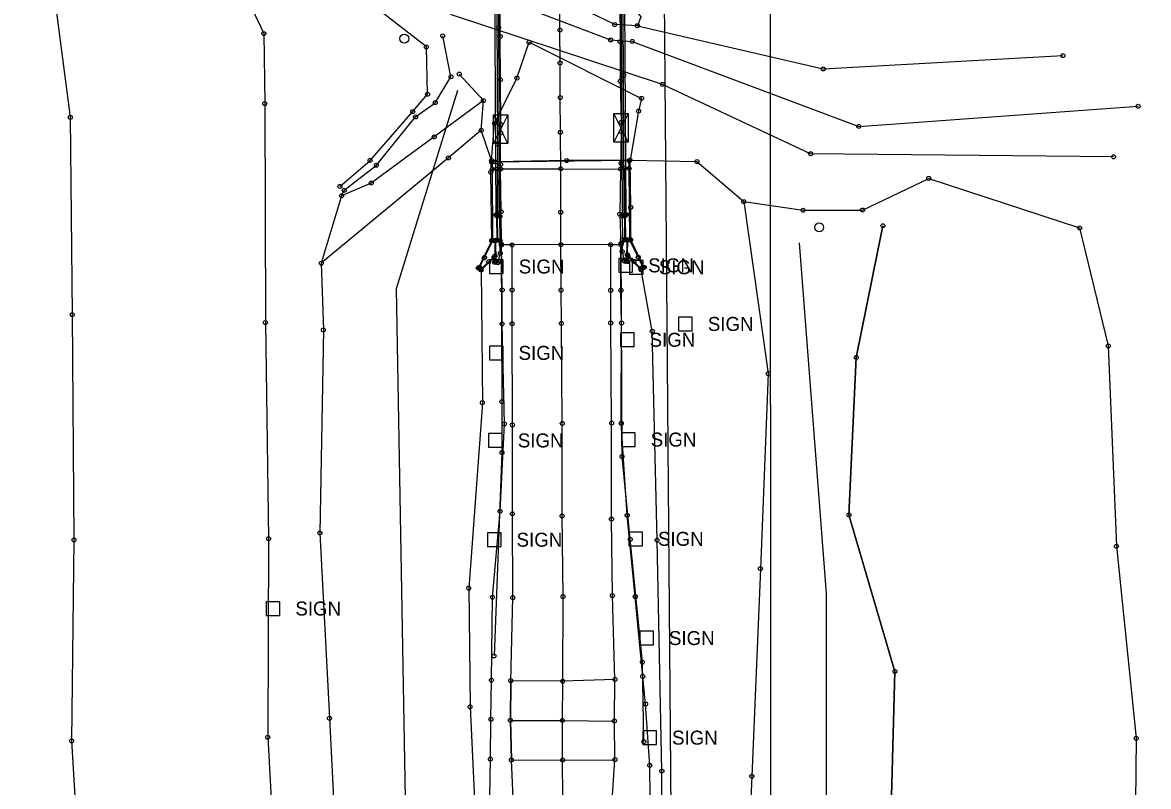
# Model space of a CAD drawing. Extents: x 23349949 to 23380641, y 6790552 to 6802878.
# Drawn here: x 23379697 to 23379978.9, y 6801650.8 to 6801841.9 of the extents above; entities that cross this region are included whole.
import ezdxf

# ---------------------------------------------------------------- set-up
doc = ezdxf.new("R2010")
doc.units = 0
for name, color, linetype in [('Bridge', 7, 'Continuous'), ('Default', 7, 'Continuous'), ('EXT_BL', 7, 'Continuous'), ('EXT_C', 7, 'Continuous'), ('EXT_CON', 7, 'Continuous'), ('EXT_D', 7, 'Continuous'), ('EXT_EP', 7, 'Continuous'), ('EXT_EW', 7, 'Continuous'), ('EXT_RIP', 7, 'Continuous'), ('EXT_SH', 7, 'Continuous'), ('Natural', 7, 'Continuous'), ('Roadways', 7, 'Continuous'), ('Section Lines', 7, 'Continuous'), ('SurControl', 7, 'Continuous'), ('SurPointsNonDTM', 7, 'Continuous'), ('SurRoadPoints', 7, 'Continuous'), ('SurSurveyPoints', 7, 'Continuous'), ('SurUtilityStructureCell', 7, 'Continuous'), ('UtilitiesBelowGround', 7, 'Continuous')]:
    doc.layers.add(name, color=color, linetype=linetype)

msp = doc.modelspace()

# ---------------------------------------------------------------- linework, layer by layer
at = {"layer": 'Bridge'}
for points in [[(23379814.83, 6801910.41), (23379814.87, 6801905.21), (23379815.27, 6801905.15), (23379815.35, 6801898.73), (23379815.45, 6801898.69), (23379815.66, 6801859.02), (23379815.96, 6801811.56), (23379816.02, 6801793.68), (23379815.84, 6801793.6), (23379815.92, 6801787.43), (23379815.4, 6801787.33), (23379815.49, 6801782.15), (23379816.23, 6801782.19), (23379816.62, 6801784.17), (23379816.59, 6801787.37), (23379816.53, 6801793.43), (23379816.24, 6801840.68), (23379815.98, 6801886.75), (23379815.92, 6801899.2), (23379815.94, 6801905.19), (23379815.96, 6801908.06), (23379815.42, 6801910.39)], [(23379848.31, 6801782.28), (23379848.38, 6801787.45), (23379847.85, 6801787.53), (23379847.84, 6801793.59), (23379847.64, 6801793.6), (23379847.49, 6801828.75), (23379847.2, 6801874.28), (23379847.05, 6801899.2), (23379847.23, 6801899.24), (23379847.26, 6801905.19), (23379847.75, 6801905.3), (23379847.7, 6801910.43), (23379846.98, 6801910.4), (23379846.55, 6801908.46), (23379846.57, 6801905.18), (23379846.59, 6801899.38), (23379846.88, 6801846.3), (23379847.19, 6801793.54), (23379847.21, 6801787.57), (23379847.15, 6801784.62), (23379847.64, 6801782.32)]]:
    msp.add_lwpolyline(points, close=True, dxfattribs=at)
at = {"layer": 'Default'}
for points in [[(23379831.81, 6801786.36), (23379831.76, 6801794.46), (23379831.79, 6801805.32), (23379831.69, 6801814.45), (23379831.67, 6801823.15), (23379831.62, 6801831.78), (23379831.56, 6801840.02), (23379831.43, 6801848.98), (23379831.5, 6801858.83), (23379831.27, 6801869.49), (23379831.42, 6801879.79), (23379831.28, 6801886.87), (23379831.24, 6801896.67), (23379831.13, 6801905.9)], [(23379815.61, 6801793.82), (23379815.02, 6801898.51)], [(23379848.16, 6801793.83), (23379847.48, 6801898.81)], [(23379846.57, 6801846.67), (23379846.64, 6801837.15), (23379846.66, 6801827.25), (23379846.91, 6801816.96), (23379846.91, 6801814.59), (23379846.74, 6801805.27), (23379846.54, 6801793.96), (23379846.83, 6801786.31), (23379844.29, 6801786.32), (23379831.81, 6801786.36), (23379819.6, 6801786.29), (23379816.92, 6801786.27), (23379816.88, 6801794.57), (23379816.71, 6801805.29), (23379816.71, 6801814.31), (23379816.77, 6801816.42), (23379816.68, 6801827.59), (23379816.63, 6801838.44), (23379816.55, 6801849.66)], [(23379816.87, 6801786.53), (23379817.05, 6801747.06), (23379817.05, 6801734.31), (23379815.07, 6801683.45)], [(23379852.58, 6801662), (23379852.22, 6801681.88), (23379849.16, 6801712.62), (23379847.12, 6801733.34), (23379846.9, 6801786.68)]]:
    msp.add_lwpolyline(points, dxfattribs=at)
at = {"layer": 'EXT_BL'}
for points in [[(23379703.1, 6801920.29), (23379702.18, 6801870.03), (23379709, 6801818.22), (23379709.48, 6801768.84), (23379709.92, 6801712.49), (23379709.34, 6801662.19), (23379712.14, 6801615.26), (23379714.4, 6801568.49), (23379697.04, 6801486.66)], [(23379776.48, 6801800.93), (23379784.04, 6801807.41), (23379794.71, 6801819.64), (23379798.43, 6801823.96), (23379798.13, 6801835.82), (23379770.13, 6801857.58), (23379767.46, 6801860.5), (23379737.65, 6801885.91), (23379703.1, 6801920.29)], [(23379746.93, 6801861.44), (23379757.45, 6801839.17), (23379757.68, 6801821.63), (23379757.83, 6801766.85), (23379758.62, 6801712.77), (23379758.42, 6801663.1), (23379760.97, 6801616.65), (23379762.46, 6801572), (23379761.99, 6801495.88)], [(23379776.9, 6801798.56), (23379777.57, 6801799.95), (23379785.63, 6801806.22), (23379795.45, 6801818.3), (23379800.36, 6801821.86), (23379804.3, 6801828.34), (23379802.23, 6801838.59)], [(23379816.03, 6801781.81), (23379815.25, 6801781.91), (23379815.04, 6801783.12), (23379811.82, 6801779.98), (23379811.17, 6801780.48), (23379814.49, 6801787.34), (23379814.27, 6801804.47), (23379814.47, 6801807.38), (23379811.86, 6801814.96), (23379812.43, 6801822.38), (23379806.38, 6801829.02)], [(23379812.43, 6801822.38), (23379800.09, 6801813.3), (23379784.33, 6801801.75), (23379776.9, 6801798.56), (23379771.83, 6801781.7)], [(23379811.86, 6801814.96), (23379803.64, 6801808.04), (23379771.83, 6801781.7), (23379772.35, 6801765.01), (23379771.47, 6801714.18), (23379771.48, 6801714.19), (23379773.88, 6801667.84), (23379776.35, 6801617.55), (23379776.91, 6801566.43), (23379779.21, 6801501.08)], [(23379849.15, 6801807.49), (23379833.25, 6801807.39), (23379815.5, 6801807.04), (23379814.47, 6801807.38)], [(23379851.87, 6801780.05), (23379852.67, 6801780.67), (23379849.3, 6801787.56), (23379849.29, 6801795.69), (23379849.15, 6801807.49), (23379865.87, 6801807.13), (23379877.6, 6801797.12), (23379892.44, 6801794.97), (23379907.31, 6801795), (23379923.88, 6801802.93), (23379961.65, 6801790.54)], [(23379816.71, 6801805.29), (23379831.79, 6801805.32), (23379846.74, 6801805.27)], [(23379877.6, 6801797.12), (23379883.73, 6801754.07), (23379881.76, 6801705.27), (23379879.61, 6801653.36), (23379877.45, 6801603.84), (23379879.08, 6801551.92), (23379880.22, 6801500.65)], [(23379921.53, 6801478.35), (23379918.04, 6801518.9), (23379919.73, 6801560.1), (23379911.12, 6801600.29), (23379914.15, 6801632.72), (23379915.42, 6801679.56), (23379903.91, 6801718.73), (23379905.76, 6801758.12), (23379912.41, 6801791.06)], [(23379961.65, 6801790.54), (23379968.85, 6801761.01), (23379970.88, 6801710.89), (23379975.83, 6801662.84), (23379975.22, 6801606.12), (23379978.9, 6801558.4), (23379972.44, 6801483.27)], [(23379857.85, 6801498.08), (23379857.65, 6801549.54), (23379857.24, 6801605.84), (23379857.08, 6801654.63), (23379855.9, 6801712.41), (23379854.7, 6801764.68), (23379851.87, 6801780.05), (23379848.61, 6801783.39), (23379848.48, 6801782.12), (23379847.85, 6801782.14)], [(23379811.82, 6801779.98), (23379812.16, 6801746.8), (23379808.74, 6801700.4), (23379809.09, 6801670.71), (23379810.92, 6801631.35), (23379810.84, 6801581.92), (23379810.59, 6801538.25), (23379810.38, 6801494.02)]]:
    msp.add_lwpolyline(points, dxfattribs=at)
at = {"layer": 'EXT_C'}
msp.add_lwpolyline([(23379833.11, 6801506.12), (23379832.79, 6801538.15), (23379832.81, 6801560.52), (23379832.69, 6801582.8), (23379832.58, 6801604.47), (23379832.48, 6801625.87), (23379832.33, 6801647.85), (23379832.25, 6801657.38), (23379832.21, 6801667.3), (23379832.28, 6801677.12), (23379832.35, 6801698.29), (23379832.11, 6801718.47), (23379832.17, 6801741.62), (23379831.95, 6801766.64), (23379831.84, 6801774.96), (23379831.81, 6801786.36)], dxfattribs=at)
at = {"layer": 'EXT_CON'}
msp.add_lwpolyline([(23379848.9, 6801805.42), (23379848.92, 6801807.36), (23379814.49, 6801806.98), (23379814.66, 6801805.22)], dxfattribs=at)
for points in [[(23379811.79, 6801780.24), (23379811.4, 6801780.66), (23379812.61, 6801783.03), (23379812.69, 6801783.14), (23379814.75, 6801787.38), (23379814.66, 6801805.22), (23379815.85, 6801805.26), (23379815.89, 6801793.73), (23379815.71, 6801793.6), (23379815.79, 6801787.46), (23379815.29, 6801787.44), (23379815.28, 6801783.5), (23379813.76, 6801782.06)], [(23379851.84, 6801780.4), (23379852.35, 6801780.71), (23379851.22, 6801783.13), (23379851.18, 6801783.2), (23379849.07, 6801787.49), (23379848.9, 6801805.42), (23379847.73, 6801805.48), (23379847.77, 6801793.73), (23379847.93, 6801793.68), (23379847.95, 6801787.6), (23379848.49, 6801787.57), (23379848.43, 6801783.84), (23379850.1, 6801782.17)], [(23379819.42, 6801657.42), (23379832.25, 6801657.38), (23379845.34, 6801657.48), (23379845.21, 6801667.16), (23379845.34, 6801677.56), (23379832.28, 6801677.12), (23379819.26, 6801677.25), (23379819.18, 6801667.32)]]:
    msp.add_lwpolyline(points, close=True, dxfattribs=at)
at = {"layer": 'EXT_D'}
for p, q in [((23379898.3, 6801699.04), (23379891.52, 6801786.79)), ((23379898.3, 6801496.16), (23379898.3, 6801699.04))]:
    msp.add_line(p, q, dxfattribs=at)
for points in [[(23379716.88, 6801938.56), (23379783.77, 6801873.05), (23379807.83, 6801852.6), (23379824.65, 6801845.04), (23379844.27, 6801837.55), (23379849.69, 6801837.18), (23379906.39, 6801815.92), (23379976.3, 6801820.96)], [(23379793.51, 6801494.6), (23379794.74, 6801546.37), (23379793.6, 6801609.98), (23379790.63, 6801775.37), (23379806.04, 6801824.96)]]:
    msp.add_lwpolyline(points, dxfattribs=at)
at = {"layer": 'EXT_EP'}
for points in [[(23379820.67, 6801506.94), (23379820.4, 6801537.92), (23379820.29, 6801561.41), (23379820.22, 6801582.8), (23379819.98, 6801604.58), (23379819.95, 6801625.47), (23379819.9, 6801647.82), (23379819.42, 6801657.42), (23379819.18, 6801667.32), (23379819.26, 6801677.25), (23379819.77, 6801698.03), (23379819.68, 6801719.01), (23379819.66, 6801741.23), (23379819.61, 6801766.55), (23379819.6, 6801775), (23379819.6, 6801786.29)], [(23379845.18, 6801510.36), (23379845.15, 6801538.43), (23379844.89, 6801559.01), (23379844.87, 6801582.96), (23379844.91, 6801604.33), (23379844.79, 6801625.84), (23379844.64, 6801647.35), (23379845.34, 6801657.48), (23379845.21, 6801667.16), (23379845.34, 6801677.56), (23379844.69, 6801698.54), (23379844.48, 6801717.68), (23379844.52, 6801741.69), (23379844.29, 6801766.73), (23379844.29, 6801774.92), (23379844.29, 6801786.32)]]:
    msp.add_lwpolyline(points, dxfattribs=at)
at = {"layer": 'EXT_EW'}
for points in [[(23379970.15, 6801808.32), (23379894.32, 6801809.09), (23379857.26, 6801826.44), (23379804.4, 6801843.87), (23379780.59, 6801866.66), (23379707.76, 6801932.18)], [(23379850.96, 6801841.13), (23379897.47, 6801830.3), (23379957.47, 6801833.63)]]:
    msp.add_lwpolyline(points, dxfattribs=at)
at = {"layer": 'EXT_RIP'}
for points in [[(23379846.86, 6801877.14), (23379844, 6801867.98), (23379840.23, 6801863.95), (23379841.16, 6801856.51), (23379851.79, 6801843.36), (23379850.97, 6801841.13), (23379845.29, 6801841.41), (23379834.85, 6801846.44), (23379830.07, 6801850.42), (23379820.55, 6801850.16), (23379807.1, 6801859.67), (23379799.92, 6801867.87), (23379801.87, 6801871.86), (23379808.43, 6801866.75), (23379811.52, 6801876.02), (23379808.2, 6801882.34), (23379825.53, 6801884.97)], [(23379833.25, 6801807.39), (23379815.5, 6801807.04), (23379814.47, 6801807.38), (23379815.21, 6801816.68), (23379820.81, 6801828.04), (23379823.87, 6801836.97), (23379852.01, 6801822.95), (23379851.27, 6801819.76), (23379849.15, 6801807.49)]]:
    msp.add_lwpolyline(points, dxfattribs=at)
at = {"layer": 'EXT_SH'}
for points in [[(23379812.05, 6801507.78), (23379812.63, 6801537.87), (23379812.74, 6801561.9), (23379812.93, 6801581.9), (23379813.55, 6801605.08), (23379813.63, 6801625.46), (23379814.05, 6801648.21), (23379814.16, 6801657.62), (23379814.31, 6801667.59), (23379814.43, 6801677.38), (23379814.68, 6801698.14), (23379816.59, 6801719.65), (23379817.67, 6801741.51), (23379817.1, 6801766.53), (23379817.1, 6801766.53), (23379817.11, 6801775.01), (23379816.92, 6801786.27)], [(23379856.05, 6801510.07), (23379855.87, 6801538.61), (23379856.07, 6801557.88), (23379855.92, 6801583.82), (23379855.68, 6801604.16), (23379855.06, 6801625.22), (23379854.13, 6801647.68), (23379854.07, 6801656.07), (23379853.02, 6801671.41), (23379852.3, 6801678.32), (23379850.44, 6801698.27), (23379848.4, 6801718.64), (23379846.94, 6801741.66), (23379847, 6801766.75), (23379846.85, 6801774.91), (23379846.83, 6801786.31)]]:
    msp.add_lwpolyline(points, dxfattribs=at)
at = {"layer": 'Natural'}
msp.add_lwpolyline([(23379912.41, 6801791.06), (23379905.76, 6801758.12), (23379903.91, 6801718.73), (23379915.42, 6801679.56), (23379914.15, 6801632.72), (23379911.12, 6801600.29), (23379919.73, 6801560.1), (23379918.04, 6801518.9), (23379921.53, 6801478.35)], dxfattribs=at)
at = {"layer": 'Roadways'}
msp.add_lwpolyline([(23379819.18, 6801667.32), (23379832.21, 6801667.3), (23379845.21, 6801667.16)], dxfattribs=at)
at = {"layer": 'Section Lines'}
msp.add_line((23379862.42, 6801260.03), (23379853.19, 6802427.68), dxfattribs=at)
at = {"layer": 'SurControl'}
for centre in [(23379792.6, 6801837.9), (23379896.47, 6801790.67)]:
    msp.add_circle(centre, 1.12, dxfattribs=at)
at = {"layer": 'SurPointsNonDTM'}
for centre in [(23379816.24, 6801840.68), (23379831.56, 6801840.02), (23379816.63, 6801838.44), (23379846.64, 6801837.15), (23379831.62, 6801831.78), (23379847.49, 6801828.75), (23379816.68, 6801827.59), (23379846.66, 6801827.25), (23379831.67, 6801823.15), (23379846.91, 6801816.96), (23379816.71, 6801814.31), (23379816.77, 6801816.42), (23379831.69, 6801814.45), (23379846.91, 6801814.59), (23379815.96, 6801811.56), (23379816.7, 6801806.42), (23379846.88, 6801806.68), (23379816.71, 6801805.29), (23379831.79, 6801805.32), (23379846.74, 6801805.27), (23379816.88, 6801794.57), (23379831.76, 6801794.46), (23379815.61, 6801793.82), (23379815.84, 6801793.6), (23379816.02, 6801793.68), (23379816.53, 6801793.43), (23379846.54, 6801793.96), (23379847.19, 6801793.54), (23379847.64, 6801793.6), (23379847.84, 6801793.59), (23379848.16, 6801793.83), (23379912.41, 6801791.06), (23379815.4, 6801787.33), (23379815.92, 6801787.43), (23379816.59, 6801787.37), (23379816.87, 6801786.53), (23379816.92, 6801786.27), (23379816.92, 6801786.27), (23379819.6, 6801786.29), (23379819.6, 6801786.29), (23379831.81, 6801786.36), (23379831.81, 6801786.36), (23379844.29, 6801786.32), (23379846.83, 6801786.31), (23379846.83, 6801786.31), (23379846.9, 6801786.68), (23379847.21, 6801787.57), (23379847.85, 6801787.53), (23379848.38, 6801787.45), (23379816.62, 6801784.17), (23379847.15, 6801784.62), (23379815.49, 6801782.15), (23379816.23, 6801782.19), (23379847.64, 6801782.32), (23379848.31, 6801782.28), (23379848.31, 6801782.28), (23379905.76, 6801758.12), (23379817.05, 6801747.06), (23379817.05, 6801734.31), (23379847.12, 6801733.34), (23379903.91, 6801718.73), (23379849.16, 6801712.62), (23379815.07, 6801683.45), (23379852.22, 6801681.88), (23379915.42, 6801679.56), (23379819.18, 6801667.32), (23379832.21, 6801667.3), (23379845.21, 6801667.16), (23379852.58, 6801662)]:
    msp.add_circle(centre, 0.5, dxfattribs=at)
at = {"layer": 'SurRoadPoints'}
for points in [[(23379815.67, 6801779.16), (23379815.67, 6801779.16), (23379817.38, 6801779.16), (23379817.38, 6801782.58), (23379813.95, 6801782.58), (23379813.95, 6801779.16), (23379815.67, 6801779.16)], [(23379848.06, 6801779.44), (23379848.06, 6801779.44), (23379849.77, 6801779.44), (23379849.77, 6801782.87), (23379846.34, 6801782.87), (23379846.34, 6801779.44), (23379848.05, 6801779.44)], [(23379850.72, 6801778.99), (23379850.72, 6801778.99), (23379852.44, 6801778.99), (23379852.44, 6801782.41), (23379849.01, 6801782.41), (23379849.01, 6801778.99), (23379850.72, 6801778.99)], [(23379862.99, 6801764.8), (23379862.99, 6801764.8), (23379864.71, 6801764.8), (23379864.71, 6801768.23), (23379861.28, 6801768.23), (23379861.28, 6801764.8), (23379862.99, 6801764.8)], [(23379848.41, 6801760.84), (23379848.41, 6801760.84), (23379850.12, 6801760.84), (23379850.12, 6801764.26), (23379846.7, 6801764.26), (23379846.7, 6801760.84), (23379848.41, 6801760.84)], [(23379815.61, 6801757.55), (23379815.61, 6801757.55), (23379817.33, 6801757.55), (23379817.33, 6801760.98), (23379813.9, 6801760.98), (23379813.9, 6801757.55), (23379815.61, 6801757.55)], [(23379815.42, 6801735.65), (23379815.42, 6801735.65), (23379817.13, 6801735.65), (23379817.13, 6801739.07), (23379813.71, 6801739.07), (23379813.71, 6801735.65), (23379815.42, 6801735.65)], [(23379848.68, 6801735.87), (23379848.68, 6801735.87), (23379850.4, 6801735.87), (23379850.4, 6801739.29), (23379846.97, 6801739.29), (23379846.97, 6801735.87), (23379848.68, 6801735.87)], [(23379815.11, 6801710.81), (23379815.11, 6801710.81), (23379816.82, 6801710.81), (23379816.82, 6801714.23), (23379813.4, 6801714.23), (23379813.4, 6801710.81), (23379815.11, 6801710.81)], [(23379850.51, 6801711.02), (23379850.51, 6801711.02), (23379852.22, 6801711.02), (23379852.22, 6801714.45), (23379848.79, 6801714.45), (23379848.79, 6801711.02), (23379850.51, 6801711.02)], [(23379759.73, 6801693.59), (23379759.73, 6801693.59), (23379761.45, 6801693.59), (23379761.45, 6801697.02), (23379758.02, 6801697.02), (23379758.02, 6801693.59), (23379759.73, 6801693.59)], [(23379853.25, 6801686.2), (23379853.25, 6801686.2), (23379854.96, 6801686.2), (23379854.96, 6801689.62), (23379851.54, 6801689.62), (23379851.54, 6801686.2), (23379853.25, 6801686.2)], [(23379854.02, 6801661.29), (23379854.02, 6801661.29), (23379855.74, 6801661.29), (23379855.74, 6801664.71), (23379852.31, 6801664.71), (23379852.31, 6801661.29), (23379854.02, 6801661.29)]]:
    msp.add_lwpolyline(points, dxfattribs=at)
at = {"layer": 'SurSurveyPoints'}
for centre in [(23379845.29, 6801841.41), (23379850.97, 6801841.13), (23379850.96, 6801841.13), (23379757.45, 6801839.17), (23379802.23, 6801838.59), (23379823.87, 6801836.97), (23379844.27, 6801837.55), (23379849.69, 6801837.18), (23379798.13, 6801835.82), (23379957.47, 6801833.63), (23379804.3, 6801828.34), (23379806.38, 6801829.02), (23379897.47, 6801830.3), (23379820.81, 6801828.04), (23379857.26, 6801826.44), (23379798.43, 6801823.96), (23379852.01, 6801822.95), (23379757.68, 6801821.63), (23379800.36, 6801821.86), (23379812.43, 6801822.38), (23379812.43, 6801822.38), (23379851.27, 6801819.76), (23379976.3, 6801820.96), (23379709, 6801818.22), (23379794.71, 6801819.64), (23379795.45, 6801818.3), (23379811.86, 6801814.96), (23379811.86, 6801814.96), (23379815.21, 6801816.68), (23379906.39, 6801815.92), (23379800.09, 6801813.3), (23379894.32, 6801809.09), (23379784.04, 6801807.41), (23379785.63, 6801806.22), (23379803.64, 6801808.04), (23379814.47, 6801807.38), (23379814.47, 6801807.38), (23379814.47, 6801807.38), (23379814.49, 6801806.98), (23379815.5, 6801807.04), (23379815.5, 6801807.04), (23379833.25, 6801807.39), (23379833.25, 6801807.39), (23379848.92, 6801807.36), (23379849.15, 6801807.49), (23379849.15, 6801807.49), (23379849.15, 6801807.49), (23379865.87, 6801807.13), (23379970.15, 6801808.32), (23379814.27, 6801804.47), (23379814.66, 6801805.22), (23379814.66, 6801805.22), (23379815.85, 6801805.26), (23379816.71, 6801805.29), (23379831.79, 6801805.32), (23379846.74, 6801805.27), (23379847.73, 6801805.48), (23379848.9, 6801805.42), (23379848.9, 6801805.42), (23379923.88, 6801802.93), (23379776.48, 6801800.93), (23379777.57, 6801799.95), (23379784.33, 6801801.75), (23379776.9, 6801798.56), (23379776.9, 6801798.56), (23379877.6, 6801797.12), (23379877.6, 6801797.12), (23379849.29, 6801795.69), (23379892.44, 6801794.97), (23379907.31, 6801795), (23379815.71, 6801793.6), (23379815.89, 6801793.73), (23379847.77, 6801793.73), (23379847.93, 6801793.68), (23379912.41, 6801791.06), (23379961.65, 6801790.54), (23379961.65, 6801790.54), (23379814.49, 6801787.34), (23379814.75, 6801787.38), (23379815.29, 6801787.44), (23379815.79, 6801787.46), (23379816.92, 6801786.27), (23379819.6, 6801786.29), (23379831.81, 6801786.36), (23379844.29, 6801786.32), (23379846.83, 6801786.31), (23379847.95, 6801787.6), (23379848.49, 6801787.57), (23379849.07, 6801787.49), (23379849.3, 6801787.56), (23379812.61, 6801783.03), (23379812.69, 6801783.14), (23379815.04, 6801783.12), (23379815.28, 6801783.5), (23379848.43, 6801783.84), (23379848.61, 6801783.39), (23379851.18, 6801783.2), (23379851.22, 6801783.13), (23379771.83, 6801781.7), (23379771.83, 6801781.7), (23379811.17, 6801780.48), (23379811.4, 6801780.66), (23379811.79, 6801780.24), (23379811.79, 6801780.24), (23379813.76, 6801782.06), (23379815.25, 6801781.91), (23379816.03, 6801781.81), (23379847.85, 6801782.14), (23379848.48, 6801782.12), (23379850.1, 6801782.17), (23379851.84, 6801780.4), (23379851.84, 6801780.4), (23379852.35, 6801780.71), (23379852.67, 6801780.67), (23379811.82, 6801779.98), (23379811.82, 6801779.98), (23379851.87, 6801780.05), (23379851.87, 6801780.05), (23379817.11, 6801775.01), (23379819.6, 6801775), (23379831.84, 6801774.96), (23379844.29, 6801774.92), (23379846.85, 6801774.91), (23379709.48, 6801768.84), (23379757.83, 6801766.85), (23379817.1, 6801766.53), (23379817.1, 6801766.53), (23379819.61, 6801766.55), (23379831.95, 6801766.64), (23379844.29, 6801766.73), (23379847, 6801766.75), (23379772.35, 6801765.01), (23379854.7, 6801764.68), (23379968.85, 6801761.01), (23379905.76, 6801758.12), (23379883.73, 6801754.07), (23379812.16, 6801746.8), (23379817.67, 6801741.51), (23379819.66, 6801741.23), (23379832.17, 6801741.62), (23379844.52, 6801741.69), (23379846.94, 6801741.66), (23379816.59, 6801719.65), (23379819.68, 6801719.01), (23379832.11, 6801718.47), (23379848.4, 6801718.64), (23379903.91, 6801718.73), (23379844.48, 6801717.68), (23379758.62, 6801712.77), (23379771.47, 6801714.18), (23379771.48, 6801714.19), (23379709.92, 6801712.49), (23379855.9, 6801712.41), (23379970.88, 6801710.89), (23379881.76, 6801705.27), (23379808.74, 6801700.4), (23379844.69, 6801698.54), (23379814.68, 6801698.14), (23379819.77, 6801698.03), (23379832.35, 6801698.29), (23379850.44, 6801698.27), (23379915.42, 6801679.56), (23379814.43, 6801677.38), (23379819.26, 6801677.25), (23379819.26, 6801677.25), (23379832.28, 6801677.12), (23379832.28, 6801677.12), (23379845.34, 6801677.56), (23379845.34, 6801677.56), (23379852.3, 6801678.32), (23379809.09, 6801670.71), (23379853.02, 6801671.41), (23379773.88, 6801667.84), (23379814.31, 6801667.59), (23379819.18, 6801667.32), (23379819.18, 6801667.32), (23379832.21, 6801667.3), (23379845.21, 6801667.16), (23379845.21, 6801667.16), (23379709.34, 6801662.19), (23379758.42, 6801663.1), (23379975.83, 6801662.84), (23379814.16, 6801657.62), (23379819.42, 6801657.42), (23379819.42, 6801657.42), (23379819.42, 6801657.42), (23379832.25, 6801657.38), (23379832.25, 6801657.38), (23379845.34, 6801657.48), (23379845.34, 6801657.48), (23379854.07, 6801656.07), (23379857.08, 6801654.63), (23379879.61, 6801653.36)]:
    msp.add_circle(centre, 0.5, dxfattribs=at)
at = {"layer": 'SurUtilityStructureCell'}
for points in [[(23379818.54, 6801811.65), (23379814.94, 6801811.65), (23379814.94, 6801818.85), (23379818.54, 6801818.85)], [(23379848.66, 6801811.98), (23379845.06, 6801811.98), (23379845.06, 6801819.18), (23379848.66, 6801819.18)]]:
    msp.add_lwpolyline(points, close=True, dxfattribs=at)
for points in [[(23379818.54, 6801811.65), (23379814.94, 6801818.85), (23379818.54, 6801818.85), (23379814.94, 6801811.65)], [(23379848.66, 6801811.98), (23379845.06, 6801819.18), (23379848.66, 6801819.18), (23379845.06, 6801811.98)]]:
    msp.add_lwpolyline(points, dxfattribs=at)
at = {"layer": 'UtilitiesBelowGround'}
msp.add_line((23379884.41, 6801592.39), (23379884.28, 6801871.88), dxfattribs=at)

# ---------------------------------------------------------------- texts
at = {"layer": 'SurRoadPoints'}
for p in [(23379821.27, 6801779.12), (23379853.66, 6801779.41), (23379856.33, 6801778.95), (23379868.6, 6801764.76), (23379854.01, 6801760.8), (23379821.22, 6801757.52), (23379821.03, 6801735.61), (23379854.29, 6801735.83), (23379820.72, 6801710.77), (23379856.11, 6801710.99), (23379765.34, 6801693.56), (23379858.86, 6801686.16), (23379859.63, 6801661.25)]:
    msp.add_text('SIGN', height=3.498, dxfattribs=at).set_placement(p)

doc.saveas('drawing.dxf')
